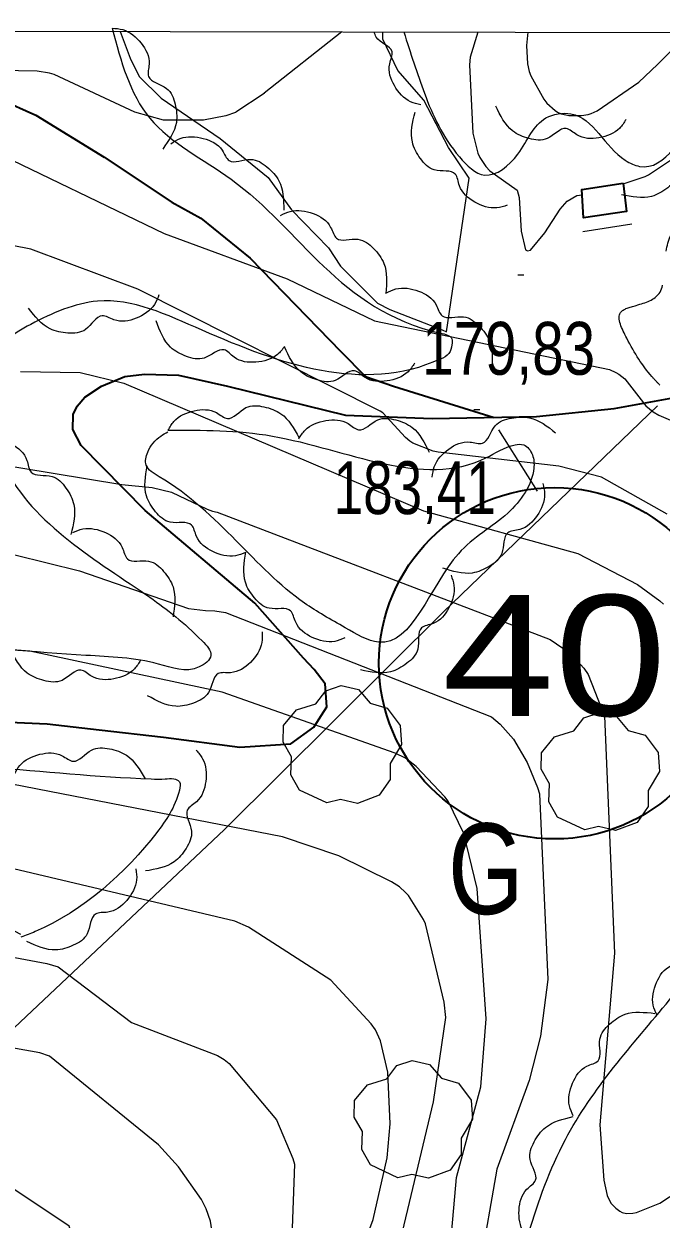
# Model space of a CAD drawing. Extents: x 483847 to 488453, y 4383581 to 4386795.
# Drawn here: x 484732 to 484837.5, y 4386250.2 to 4386448.1 of the extents above; entities that cross this region are included whole.
import ezdxf
from ezdxf.enums import TextEntityAlignment as Align

# ---------------------------------------------------------------- set-up
doc = ezdxf.new("R2010")
doc.units = 0
doc.header["$LTSCALE"] = 3.8
doc.linetypes.add('LONG_DASHED', pattern=[7.5, 6, -1.5])
for name, color, linetype, lineweight in [('1', 7, 'Continuous', 13), ('13', 7, 'Continuous', 25), ('25', 7, 'LONG_DASHED', 25), ('27', 7, 'Continuous', 25), ('29', 7, 'Continuous', 13), ('38', 7, 'Continuous', 25), ('47', 7, 'Continuous', 35), ('51', 7, 'Continuous', 13), ('6', 7, 'Continuous', 35), ('7', 7, 'Continuous', 13), ('8', 7, 'Continuous', 25), ('9', 7, 'Continuous', 13)]:
    doc.layers.add(name, color=color, linetype=linetype, lineweight=lineweight)
doc.layers.add('31', color=7, linetype='Continuous')

msp = doc.modelspace()

# ---------------------------------------------------------------- linework, layer by layer
at = {"layer": '1'}
msp.add_lwpolyline([(484105.5, 4386448.1), (487681.9, 4386441.2), (487678, 4384129), (484100.5, 4384135.8)], close=True, dxfattribs=at)
at = {"layer": '25'}
for points in [[(484747.95, 4386446.86), (484749.61, 4386442.44), (484751.13, 4386439.39), (484754.74, 4386435.79), (484764.53, 4386429.14), (484772.48, 4386422.68), (484776.35, 4386417.29), (484782.48, 4386411), (484784.45, 4386407.99), (484790.56, 4386401.85), (484792.59, 4386400.83), (484801.26, 4386397.46), (484802.01, 4386397.1)], [(484805.72, 4386422.55), (484802.3, 4386427.61), (484798.25, 4386435.48), (484793.95, 4386440.41), (484791.47, 4386445.55), (484791.43, 4386446.78)]]:
    msp.add_lwpolyline(points, dxfattribs=at)
at = {"layer": '27'}
for points in [[(484746.63, 4386447.39), (484752.88, 4386432.48), (484766.34, 4386422.39), (484800.95, 4386396.9), (484802.87, 4386395.94), (484802.87, 4386394.98), (484802.39, 4386393.53), (484800.95, 4386392.57), (484761.53, 4386397.38), (484744.23, 4386402.19), (484733.18, 4386398.34), (484728.85, 4386395.46), (484725.49, 4386388.73), (484726.45, 4386381.51), (484728.85, 4386374.78), (484752.88, 4386353.14), (484761.53, 4386345.93), (484762.98, 4386343.52), (484761.05, 4386341.6), (484754.32, 4386342.08), (484742.31, 4386343.52), (484690.4, 4386345.45), (484675.02, 4386341.12), (484668.29, 4386335.35), (484663.48, 4386328.62), (484661.08, 4386320.92), (484664.93, 4386312.27), (484676.46, 4386304.09), (484704.34, 4386291.59), (484707.22, 4386288.22), (484707.7, 4386285.82), (484701.46, 4386281.49), (484697.61, 4386279.57), (484688.96, 4386277.65), (484639.45, 4386259.85), (484605.33, 4386235.81), (484575.53, 4386212.25), (484545.25, 4386166.57), (484527.47, 4386135.79), (484521.7, 4386129.06)], [(484746.63, 4386447.39), (484748.39, 4386447.15), (484751.44, 4386444.89), (484752.76, 4386441.45), (484752.68, 4386439.4), (484755.64, 4386437.43), (484757.07, 4386434.81), (484757.27, 4386431.79), (484755.01, 4386427.37)], [(484797.74, 4386434.68), (484796.04, 4386435.19), (484793.37, 4386437.88), (484792.59, 4386441.49), (484792.98, 4386443.5), (484790.35, 4386445.9), (484790.03, 4386446.78)], [(484794.93, 4386446.77), (484798.34, 4386436.61), (484804.13, 4386426.07), (484808.32, 4386423.07), (484813.8, 4386426.55), (484818.45, 4386432.52), (484822.59, 4386433.2), (484831.59, 4386425.51), (484833.94, 4386424.51), (484844.75, 4386433.87), (484856.83, 4386439.39), (484860.54, 4386439.27), (484866.6, 4386440.67), (484868.5, 4386446.63)], [(484845.79, 4386435.65), (484846.29, 4386433.95), (484845.49, 4386430.24), (484842.89, 4386427.62), (484840.98, 4386426.85), (484840.4, 4386423.34), (484838.6, 4386420.97), (484835.93, 4386419.54), (484830.97, 4386419.79)], [(484831.71, 4386432.27), (484830.66, 4386430.84), (484827.22, 4386429.24), (484823.56, 4386429.72), (484821.8, 4386430.78), (484818.66, 4386429.12), (484815.67, 4386429.12), (484812.93, 4386430.38), (484810.13, 4386434.48)], [(484812.05, 4386418.08), (484810.33, 4386417.64), (484806.66, 4386418.59), (484804.14, 4386421.29), (484803.45, 4386423.22), (484799.97, 4386423.94), (484797.66, 4386425.83), (484796.34, 4386428.55), (484796.78, 4386433.49)], [(484756.38, 4386428.26), (484757.93, 4386429.12), (484761.73, 4386429.13), (484764.85, 4386427.17), (484766.01, 4386425.47), (484769.56, 4386425.67), (484772.27, 4386424.42), (484774.24, 4386422.12), (484775.07, 4386417.23)], [(484774.5, 4386416.37), (484776.13, 4386417.06), (484779.91, 4386416.69), (484782.81, 4386414.41), (484783.79, 4386412.6), (484787.34, 4386412.43), (484789.91, 4386410.91), (484791.63, 4386408.42), (484791.95, 4386403.47)], [(484791.97, 4386403.5), (484793.6, 4386404.2), (484797.38, 4386403.83), (484800.29, 4386401.56), (484801.27, 4386399.75), (484804.82, 4386399.59), (484807.39, 4386398.07), (484809.12, 4386395.59), (484809.45, 4386390.64)], [(484754.4, 4386403.25), (484753.66, 4386401.63), (484750.62, 4386399.36), (484746.94, 4386399.09), (484745, 4386399.77), (484742.26, 4386397.5), (484739.33, 4386396.9), (484736.39, 4386397.58), (484732.81, 4386401.01)], [(484775.19, 4386394.68), (484774.01, 4386393.35), (484770.44, 4386392.08), (484766.84, 4386392.91), (484765.18, 4386394.12), (484761.9, 4386392.76), (484758.93, 4386393.04), (484756.31, 4386394.56), (484753.91, 4386398.9)], [(484796.71, 4386391.9), (484795.63, 4386390.49), (484792.15, 4386388.97), (484788.5, 4386389.54), (484786.77, 4386390.64), (484783.58, 4386389.06), (484780.6, 4386389.13), (484777.88, 4386390.46), (484775.18, 4386394.62)], [(484755.89, 4386380.8), (484756.87, 4386382.28), (484760.24, 4386384.03), (484763.91, 4386383.72), (484765.72, 4386382.75), (484768.79, 4386384.55), (484771.77, 4386384.69), (484774.57, 4386383.55), (484777.56, 4386379.59)], [(484777.54, 4386379.39), (484778.59, 4386380.82), (484782.04, 4386382.41), (484785.69, 4386381.92), (484787.45, 4386380.87), (484790.6, 4386382.52), (484793.59, 4386382.52), (484796.33, 4386381.25), (484799.12, 4386377.15)], [(484799.64, 4386373.02), (484799.97, 4386374.76), (484802.37, 4386377.69), (484805.88, 4386378.85), (484807.93, 4386378.66), (484810.04, 4386381.52), (484812.73, 4386382.82), (484815.75, 4386382.87), (484820.05, 4386380.39)], [(484755.89, 4386380.8), (484773.19, 4386379.84), (484808.52, 4386376.23), (484813.33, 4386378.39), (484814.77, 4386378.39), (484816.21, 4386376.71), (484816.45, 4386374.55), (484812.12, 4386367.09), (484803.95, 4386360.36), (484790.74, 4386345.69), (484785.21, 4386348.1), (484778.48, 4386352.19), (484754.45, 4386373.1), (484752.28, 4386375.03), (484752.53, 4386377.19), (484754.69, 4386379.84), (484755.89, 4386380.56)], [(484724.64, 4386379.07), (484726.37, 4386379.5), (484730.03, 4386378.53), (484732.54, 4386375.82), (484733.22, 4386373.88), (484736.7, 4386373.15), (484739, 4386371.24), (484740.3, 4386368.51), (484739.83, 4386363.57)], [(484768.73, 4386360.58), (484767.04, 4386360.02), (484763.31, 4386360.71), (484760.61, 4386363.23), (484759.79, 4386365.11), (484756.26, 4386365.58), (484753.83, 4386367.31), (484752.33, 4386369.93), (484752.42, 4386374.89)], [(484817.92, 4386372.01), (484818.23, 4386370.26), (484816.99, 4386366.67), (484814.11, 4386364.37), (484812.13, 4386363.83), (484811.14, 4386360.42), (484809.07, 4386358.27), (484806.26, 4386357.16), (484801.36, 4386357.99)], [(484740.13, 4386363.87), (484741.8, 4386364.46), (484745.55, 4386363.85), (484748.3, 4386361.39), (484749.16, 4386359.52), (484752.69, 4386359.13), (484755.16, 4386357.44), (484756.72, 4386354.85), (484756.72, 4386349.89)], [(484785.17, 4386346.41), (484783.49, 4386345.84), (484779.75, 4386346.51), (484777.03, 4386349), (484776.19, 4386350.88), (484772.66, 4386351.32), (484770.22, 4386353.03), (484768.7, 4386355.64), (484768.75, 4386360.6)], [(484802.75, 4386356.81), (484803.23, 4386355.11), (484802.39, 4386351.41), (484799.77, 4386348.81), (484797.85, 4386348.07), (484797.24, 4386344.56), (484795.41, 4386342.21), (484792.73, 4386340.81), (484787.78, 4386341.11)], [(484771.46, 4386347.42), (484771.42, 4386345.65), (484769.52, 4386342.36), (484766.25, 4386340.66), (484764.2, 4386340.51), (484762.58, 4386337.35), (484760.13, 4386335.63), (484757.16, 4386335.09), (484752.52, 4386336.84)], [(484751.36, 4386342.73), (484750.33, 4386341.28), (484746.91, 4386339.63), (484743.24, 4386340.07), (484741.47, 4386341.09), (484738.35, 4386339.39), (484735.36, 4386339.35), (484732.6, 4386340.58), (484729.74, 4386344.63)], [(484700.18, 4386195.41), (484750.6, 4386216.22), (484776.67, 4386228), (484779.62, 4386225.05), (484778.78, 4386222.11), (484767.42, 4386211.17), (484761.53, 4386201.49), (484762.8, 4386188.87), (484767, 4386176.67), (484776.67, 4386171.2), (484788.03, 4386171.62), (484796.86, 4386188.03), (484811.16, 4386231.78), (484821.67, 4386263.34), (484838.91, 4386286.48), (484868.77, 4386322.24), (484889.8, 4386336.55), (484901.57, 4386337.81), (484912.09, 4386332.76), (484919.24, 4386332.76), (484928.07, 4386336.55), (484929.75, 4386336.55), (484935.22, 4386336.55), (484960.45, 4386328.13), (484990.73, 4386305.83), (485012.18, 4386295.73), (485037.41, 4386278.06), (485058.02, 4386260.39), (485061.38, 4386254.92), (485060.54, 4386248.19), (485059.28, 4386246.09), (485054.23, 4386246.93), (485039.93, 4386264.18), (485027.32, 4386274.7), (485013.02, 4386281.43), (485005.87, 4386280.17), (485002.5, 4386272.17), (485003.77, 4386259.55), (485026.05, 4386241.46), (485035.31, 4386235.15), (485042.88, 4386225.89), (485046.66, 4386209.06), (485049.61, 4386199.81), (485055.91, 4386190.97), (485066.85, 4386188.45), (485075.26, 4386188.87), (485091.66, 4386197.7), (485095.86, 4386206.54), (485096.29, 4386218.74), (485100.07, 4386226.31), (485108.9, 4386233.89), (485118.57, 4386233.89), (485133.71, 4386224.63)], [(484731.55, 4386297.31), (484695.5, 4386316.98), (484691.75, 4386321.2), (484692.69, 4386322.61), (484699.25, 4386324.95), (484753.09, 4386323.07), (484755.43, 4386323.07), (484756.84, 4386323.07), (484757.77, 4386322.61), (484757.77, 4386321.2), (484754.03, 4386314.17), (484733.89, 4386297.78), (484731.55, 4386296.84)], [(484730.41, 4386323.8), (484731.36, 4386325.3), (484734.68, 4386327.14), (484738.36, 4386326.91), (484740.19, 4386325.98), (484743.22, 4386327.85), (484746.19, 4386328.06), (484749.02, 4386326.98), (484752.1, 4386323.09)], [(484760.55, 4386327.83), (484761.61, 4386326.41), (484762.14, 4386322.65), (484760.61, 4386319.29), (484759.09, 4386317.91), (484759.77, 4386314.42), (484758.89, 4386311.57), (484756.89, 4386309.31), (484752.15, 4386307.82)], [(484750.59, 4386308.15), (484750.69, 4386306.38), (484749.06, 4386302.95), (484745.92, 4386301), (484743.89, 4386300.69), (484742.52, 4386297.41), (484740.22, 4386295.51), (484737.3, 4386294.74), (484732.53, 4386296.12)], [(484836.85, 4386283.93), (484836.22, 4386285.59), (484836.76, 4386289.35), (484839.17, 4386292.15), (484841.01, 4386293.05), (484841.34, 4386296.59), (484842.98, 4386299.09), (484845.53, 4386300.7), (484850.49, 4386300.8)], [(484822.97, 4386267.26), (484822.33, 4386268.91), (484822.85, 4386272.67), (484825.23, 4386275.49), (484827.07, 4386276.4), (484827.37, 4386279.95), (484828.99, 4386282.46), (484831.54, 4386284.08), (484836.49, 4386284.23)], [(484815.94, 4386246.61), (484814.78, 4386247.96), (484814, 4386251.67), (484815.3, 4386255.13), (484816.73, 4386256.6), (484815.83, 4386260.04), (484816.5, 4386262.95), (484818.36, 4386265.34), (484822.98, 4386267.14)]]:
    msp.add_spline(points, degree=3, dxfattribs=at)
at = {"layer": '29'}
for points in [[(484782.18, 4386319.09), (484777.64, 4386321.21), (484776.23, 4386323.75), (484776.33, 4386326.73), (484774.96, 4386329.14), (484775, 4386331.89), (484777.16, 4386334.49), (484780.35, 4386335.49), (484782, 4386337.68), (484784.57, 4386338.51), (484787.43, 4386337.86), (484789.38, 4386335.59), (484792.19, 4386334.77), (484794.32, 4386331.92), (484794.56, 4386328.79), (484792.68, 4386325.64), (484792.68, 4386322.96), (484790.86, 4386320.35), (484787.24, 4386319.01), (484784.47, 4386319.64)], [(484824.88, 4386314.61), (484820.34, 4386316.73), (484818.93, 4386319.27), (484819.03, 4386322.25), (484817.66, 4386324.66), (484817.7, 4386327.41), (484819.86, 4386330.01), (484823.05, 4386331.01), (484824.7, 4386333.2), (484827.27, 4386334.03), (484830.13, 4386333.38), (484832.08, 4386331.11), (484834.89, 4386330.29), (484837.02, 4386327.44), (484837.26, 4386324.31), (484835.38, 4386321.16), (484835.38, 4386318.48), (484833.56, 4386315.87), (484829.94, 4386314.53), (484827.17, 4386315.16)], [(484793.94, 4386257.02), (484789.4, 4386259.14), (484787.99, 4386261.68), (484788.09, 4386264.66), (484786.72, 4386267.07), (484786.76, 4386269.82), (484788.92, 4386272.42), (484792.11, 4386273.42), (484793.76, 4386275.61), (484796.33, 4386276.44), (484799.19, 4386275.79), (484801.14, 4386273.52), (484803.95, 4386272.7), (484806.08, 4386269.85), (484806.32, 4386266.72), (484804.44, 4386263.57), (484804.44, 4386260.89), (484802.62, 4386258.28), (484799, 4386256.94), (484796.23, 4386257.57)]]:
    msp.add_lwpolyline(points, close=True, dxfattribs=at)
at = {"layer": '38', "linetype": 'LONG_DASHED'}
msp.add_spline([(484837.29, 4386388.3), (484835.99, 4386389.71), (484831.82, 4386396.07), (484830.81, 4386400.3), (484833.39, 4386401.49), (484837.19, 4386403.46), (484838.06, 4386408.31), (484839.37, 4386413.73), (484843.08, 4386418.56), (484849.7, 4386421.82), (484852.7, 4386423.01)], degree=3, dxfattribs=at)
at = {"layer": '47'}
msp.add_lwpolyline([(484831.21, 4386421.75), (484831.79, 4386417.03), (484824.68, 4386416), (484824.38, 4386420.7)], close=True, dxfattribs=at)
at = {"layer": '51'}
for p, q in [((484802.01, 4386397.1), (484805.72, 4386422.55)), ((484832.67, 4386414.94), (484824.58, 4386413.65))]:
    msp.add_line(p, q, dxfattribs=at)
msp.add_lwpolyline([(484698.51, 4386251.84), (484765.24, 4386314.7), (484801.51, 4386350.75), (484836.89, 4386384.83)], dxfattribs=at)
at = {"layer": '6', "lineweight": 25}
msp.add_line((484810.58, 4386380.86), (484816.98, 4386370.74), dxfattribs=at)
at = {"layer": '6'}
for points in [[(484678.9, 4386446.99), (484680.33, 4386445.85), (484691.09, 4386444.37), (484701.51, 4386443.23), (484710.08, 4386441.49), (484718.53, 4386439.37), (484723.57, 4386437.83), (484728.11, 4386435.66), (484734.03, 4386433), (484745.31, 4386426.03), (484756.55, 4386418.6), (484761.33, 4386415.93), (484769.5, 4386409.28), (484784.5, 4386393.85), (484788.56, 4386389.73), (484793.23, 4386388.09), (484809.87, 4386382.9)], [(484724.64, 4386332.71), (484735.89, 4386332.21), (484744.5, 4386331.21), (484755.17, 4386329.99), (484767.77, 4386328.32), (484776.22, 4386328.88), (484780.04, 4386331.64), (484782.17, 4386335), (484781.89, 4386338.8), (484780.11, 4386341.21), (484778.3, 4386343.08), (484770.28, 4386352.19), (484752.12, 4386367.49), (484741.53, 4386378.26), (484740.11, 4386380.91), (484740.18, 4386383.41), (484740.83, 4386384.77), (484742.14, 4386386.31), (484744.9, 4386388.13), (484748.72, 4386389.71), (484752.02, 4386390.1), (484757.64, 4386389.92), (484765.75, 4386388.13), (484785.25, 4386383.31), (484799.6, 4386382.75), (484816.87, 4386383.07), (484829.76, 4386384.43), (484839.45, 4386386.17)]]:
    msp.add_lwpolyline(points, dxfattribs=at)
msp.add_circle((484819.9, 4386342.23), 29.1, dxfattribs=at)
at = {"layer": '7'}
for p, q in [((484813.8, 4386406.53), (484814.8, 4386406.53)), ((484806.5, 4386384.25), (484807.5, 4386384.25))]:
    msp.add_line(p, q, dxfattribs=at)
at = {"layer": '8'}
for points in [[(484784.68, 4386446.79), (484771.82, 4386436.61), (484771.82, 4386436.59), (484767.13, 4386433.46), (484767.12, 4386433.46), (484767.11, 4386433.46), (484767.08, 4386433.44), (484765.44, 4386432.89), (484761.78, 4386432.16), (484755.14, 4386432.15), (484750.39, 4386433.47), (484737.06, 4386439.71), (484736.29, 4386439.94), (484734.24, 4386440.27), (484724.86, 4386440.46), (484691.82, 4386446.17), (484689.74, 4386446.97)], [(484730.51, 4386360.15), (484741.23, 4386357.51), (484759.3, 4386351.29), (484762.11, 4386350.94), (484763.62, 4386350.9), (484765.41, 4386350.64), (484809.45, 4386333.32), (484810.9, 4386332.14), (484813.1, 4386329.65), (484815.35, 4386325.78), (484817.06, 4386321.64), (484817.36, 4386320.61), (484818.79, 4386289.86), (484817.55, 4386280.46), (484815.69, 4386273.13), (484810.31, 4386258.42), (484807.5, 4386242.33)], [(484730.87, 4386190.03), (484734.23, 4386196.76), (484757.23, 4386227.81), (484758.31, 4386229.73), (484762.8, 4386241.11), (484763.33, 4386244.58), (484763.28, 4386247.67), (484762.91, 4386249.81), (484762.23, 4386251.89), (484761.46, 4386253.41), (484757.61, 4386258.83), (484754.32, 4386262.45), (484736.27, 4386277.16), (484734.68, 4386277.71), (484725, 4386279.42)]]:
    msp.add_lwpolyline(points, dxfattribs=at)
at = {"layer": '9'}
for points in [[(484807.19, 4386446.75), (484805.89, 4386442.61), (484805.82, 4386441.32), (484806.37, 4386430.01), (484807.17, 4386426.7), (484807.51, 4386425.95), (484808.49, 4386424.48), (484809.17, 4386423.75), (484813.66, 4386420.55), (484814.03, 4386419.37), (484814.37, 4386413.8), (484815.04, 4386410.68), (484815.41, 4386410.5), (484815.87, 4386410.62), (484818.24, 4386413.51), (484820.82, 4386417.4), (484821.98, 4386418.75), (484823.58, 4386419.71), (484824.44, 4386419.77)], [(484815.48, 4386446.73), (484815.24, 4386444.55), (484815.42, 4386441.47), (484815.67, 4386440.21), (484815.95, 4386439.5), (484818.08, 4386435.63), (484818.6, 4386435), (484819.98, 4386433.74), (484820.34, 4386433.51), (484820.99, 4386433.2), (484821.73, 4386433.02), (484822.23, 4386432.95), (484824.34, 4386432.95), (484825.42, 4386433.1), (484825.94, 4386433.28), (484826.91, 4386433.7), (484833.85, 4386438.43), (484836.94, 4386441.36), (484842.17, 4386446.68)], [(484831.23, 4386421.62), (484834.85, 4386422.81), (484835.44, 4386423.12), (484839.58, 4386425.88), (484841.38, 4386427.62), (484841.97, 4386428.44), (484843.15, 4386430.51), (484848.14, 4386446.67)], [(484725.22, 4386427.88), (484755.28, 4386413.4), (484775.63, 4386405.89), (484790.06, 4386398.92), (484828.95, 4386390.87), (484830.01, 4386390.39), (484830.51, 4386390.1), (484831.52, 4386389.31), (484835.01, 4386384.87), (484836.22, 4386383.87), (484837.14, 4386383.28), (484839.07, 4386382.46)], [(484838.49, 4386366.9), (484827.62, 4386373.03), (484820.6, 4386374.87), (484800.6, 4386377.15), (484799.81, 4386377.37), (484796.44, 4386378.68), (484795.92, 4386379.01), (484795.18, 4386379.59), (484791.45, 4386383.68), (484791.03, 4386383.98), (484750.87, 4386404.19), (484733.17, 4386410.79), (484723.6, 4386412.69)], [(484731.48, 4386390.53), (484741.36, 4386390.36), (484748.56, 4386388.61), (484798.2, 4386367.47), (484823.75, 4386360.37), (484833.6, 4386355.27), (484837.31, 4386352.57), (484837.93, 4386352)], [(484709.08, 4386378.28), (484748.23, 4386371.8)], [(484748.23, 4386371.8), (484753.25, 4386371.33), (484756.45, 4386370.58), (484762.37, 4386367.74), (484763.26, 4386367.42), (484764.05, 4386367.22), (484819.15, 4386346.15), (484822.46, 4386343.88), (484824.7, 4386341.41), (484825.43, 4386340.34), (484828.16, 4386333.45), (484829.79, 4386294.2), (484827.36, 4386265.77), (484828.02, 4386256.61), (484828.59, 4386254.1), (484829.18, 4386252.82), (484830.01, 4386251.98), (484830.68, 4386251.46), (484831.06, 4386251.27), (484831.77, 4386251.12), (484832.84, 4386251.15), (484833.46, 4386251.26), (484837.28, 4386252.83), (484890.65, 4386287.81)], [(484801.11, 4386228.23), (484803.66, 4386257.08), (484807.69, 4386272.08), (484808.57, 4386283.36), (484807.04, 4386304.91), (484804.87, 4386314), (484802.28, 4386319.4), (484801.72, 4386320.11), (484796.99, 4386325.1), (484795.18, 4386326.48), (484793.52, 4386327.35), (484764.85, 4386337.45), (484733.01, 4386344.24), (484669.07, 4386349.16)], [(484777.77, 4386176.52), (484775.26, 4386178.39), (484774.45, 4386179.24), (484773.88, 4386180.07), (484773.33, 4386181.22), (484773.05, 4386182.17), (484772.28, 4386194.91), (484773.25, 4386202.64), (484775.63, 4386211.16), (484792.43, 4386238.94), (484792.74, 4386239.71), (484799.83, 4386269.57), (484801.86, 4386283.55), (484801.62, 4386286.08), (484798.52, 4386299.06), (484798.18, 4386299.76), (484795.69, 4386303.76), (484795.22, 4386304.27), (484794.2, 4386305.17), (484792.86, 4386306.04), (484784.19, 4386310.34), (484774.86, 4386313.48), (484728, 4386322.56)], [(484752.57, 4386184.55), (484754.81, 4386198.58), (484756.54, 4386202.73), (484774.03, 4386228.23), (484785.58, 4386240.5), (484786.9, 4386242.55), (484787.61, 4386244.04), (484789.86, 4386250.08), (484792.15, 4386260.33), (484792.68, 4386265.95), (484792.28, 4386274.48), (484791.09, 4386279.71), (484790.23, 4386281.51), (484789.52, 4386282.53), (484782.85, 4386289.75), (484769.2, 4386298.5), (484766.96, 4386299.5), (484683.34, 4386319.27), (484657.83, 4386318.34), (484631.02, 4386314.12), (484584.85, 4386300.05), (484574.98, 4386294.53)], [(484723.15, 4386294.89), (484735.85, 4386292.52), (484737.73, 4386291.93), (484749.85, 4386282.71), (484764.07, 4386277.27), (484765.17, 4386276.58), (484765.99, 4386275.94), (484773.84, 4386266.62), (484776.57, 4386260.19), (484776.85, 4386259.28), (484776.34, 4386245.63)], [(484743.41, 4386229.77), (484743.26, 4386237.09), (484742.58, 4386240.83), (484739.52, 4386249.02), (484724.83, 4386258.75), (484715.76, 4386262.73), (484713.62, 4386263.25), (484691.15, 4386266.37), (484690.27, 4386266.66), (484689.86, 4386266.84), (484689.26, 4386267.2), (484688.68, 4386267.75), (484686.29, 4386270.65), (484685.76, 4386271.08), (484685.25, 4386271.26), (484684.92, 4386271.32), (484684.21, 4386271.35), (484678.9, 4386270.69), (484658.61, 4386270.25), (484589.85, 4386263.82), (484586.95, 4386262.7), (484571.76, 4386254.77)]]:
    msp.add_lwpolyline(points, dxfattribs=at)

# ---------------------------------------------------------------- texts
at = {"layer": '13', "width": 1.25}
msp.add_text('40', height=20, dxfattribs=at).set_placement((484819.84, 4386333.51), align=Align.CENTER)
at = {"layer": '31', "width": 0.8}
msp.add_text('G', height=15, dxfattribs=at).set_placement((484808.49, 4386300.69), align=Align.CENTER)
at = {"layer": '7'}
for s, width, p in [('179,83', 0.8, (484797.96, 4386390)), ('183,41', 0.75, (484783.32, 4386366.92))]:
    msp.add_text(s, height=8.75, dxfattribs=dict(at, width=width)).set_placement(p)

doc.saveas('drawing.dxf')
